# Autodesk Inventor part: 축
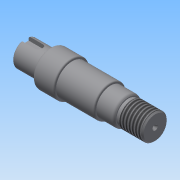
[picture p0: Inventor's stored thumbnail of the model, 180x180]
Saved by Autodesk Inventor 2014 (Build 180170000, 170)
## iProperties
Created: 2020-10
Part Number: 축
Material: 일반
Document SubType Name: Modeling
Designer: NET
Density: 1 g/cm^3
Appearance: 기본값
Author: NET
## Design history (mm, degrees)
sketch "스케치1"
  geometry: L1 (0, 0)-(102, 0); L2 (0, 0)-(0, 10); L3 (0, 10)-(20, 10); L4 (20, 10)-(20, 14); L5 (20, 14)-(37, 14); L6 (37, 14)-(37, 12.5); L7 (37, 12.5)-(67, 12.5); L8 (67, 12.5)-(67, 11); L9 (67, 11)-(81, 11); L10 (81, 11)-(81, 9.2); L11 (102, 10)-(102, 0); L12 (81, 9.2)-(82.6, 9.2); L13 (83.986, 10)-(102, 10); L14 (82.6, 9.2)-(83.986, 10)
  constraints: 28 end point, 6 parallel, 3 perpendicular, 2 horizontal, 1 vertical
  dimensions: "d0" = 102 distance of L1.start L1.end; "d1" = 20 distance of L2.end L3.end; "d2" = 17 distance of L4.end L5.end; "d3" = 30 distance of L6.end L7.end; "d4" = 14 distance of L8.end L9.end; "d5" = 20 diameter of L3 L1; "d6" = 28 diameter of L5 L1; "d7" = 25 diameter of L7 L1; "d8" = 22 diameter of L9 L1; "d20" = 18.4 diameter of L12 L1; "d22" = 20 diameter of L13 L1; "d24" = 150 deg angle of L14 L12
revolve "회전1" sketch "스케치1" stored, may be unused: angle "d10" = 90 deg
chamfer "모따기1" distance "d11" = 1; stored, may be unused: second distance "d12" = 2, angle "d13" = 45 deg
chamfer "모따기2" distance "d14" = 1; stored, may be unused: second distance "d15" = 2, angle "d16" = 45 deg
fillet "모깎기1" dims "d17" = 2
fillet "모깎기2" dims "d18" = 1
node "작업 평면1"
sketch "스케치2"
  geometry: L1 (10, -10)-(10, 10) reference; L2 (-9, 10)-(-9, -10) reference; L3 (-13, 0)-(1, 0); L4 (-13, -3)-(1, -3); L5 (1, 3)-(-13, 3); L6 (-10, -9)-(-10, 9) reference; L7 (-9, 0)-(8.901, 0); A1 r 3 centre (-13, 0) between (-13, 3) and (-13, -3); A2 r 3 centre (1, 0) between (1, -3) and (1, 3); 1 further point
  constraints: 10 end point, 4 point on circle, 4 tangent, 2 centre point, 2 midpoint, 2 perpendicular, 1 parallel, 1 point on line
  dimensions: "d30" = 14 distance of L3.start L3.end; "d31" = 6 diameter of A2; "d34" = 11 distance from line of L6 L3.end
extrude "돌출1" cut sketch "스케치2" distance "d35" = 3.5; taper "d36" = 0 deg
fillet "모깎기4" dims "d37" = 1
feature "스레드1" dims "d38" = 10, "d39" = 0
sketch "스케치4"
  geometry: C1 r 9 at (0, 0) reference; 1 further point
  constraints: 1 coincident
hole "구멍1" sketch "스케치4" at (0, 0) diameter "d43" = 2; stored, may be unused: countersink angle "d47" = 60 deg, drill point angle "d49" = 118 deg; dims "d44" = 6, "d45" = 4.25, "d46" = 2, "d48" = 3.3
node "솔리드1"
node "투영된 루프1"
node "투영된 루프3"
